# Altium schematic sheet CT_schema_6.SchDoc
size 266 x 267 mm
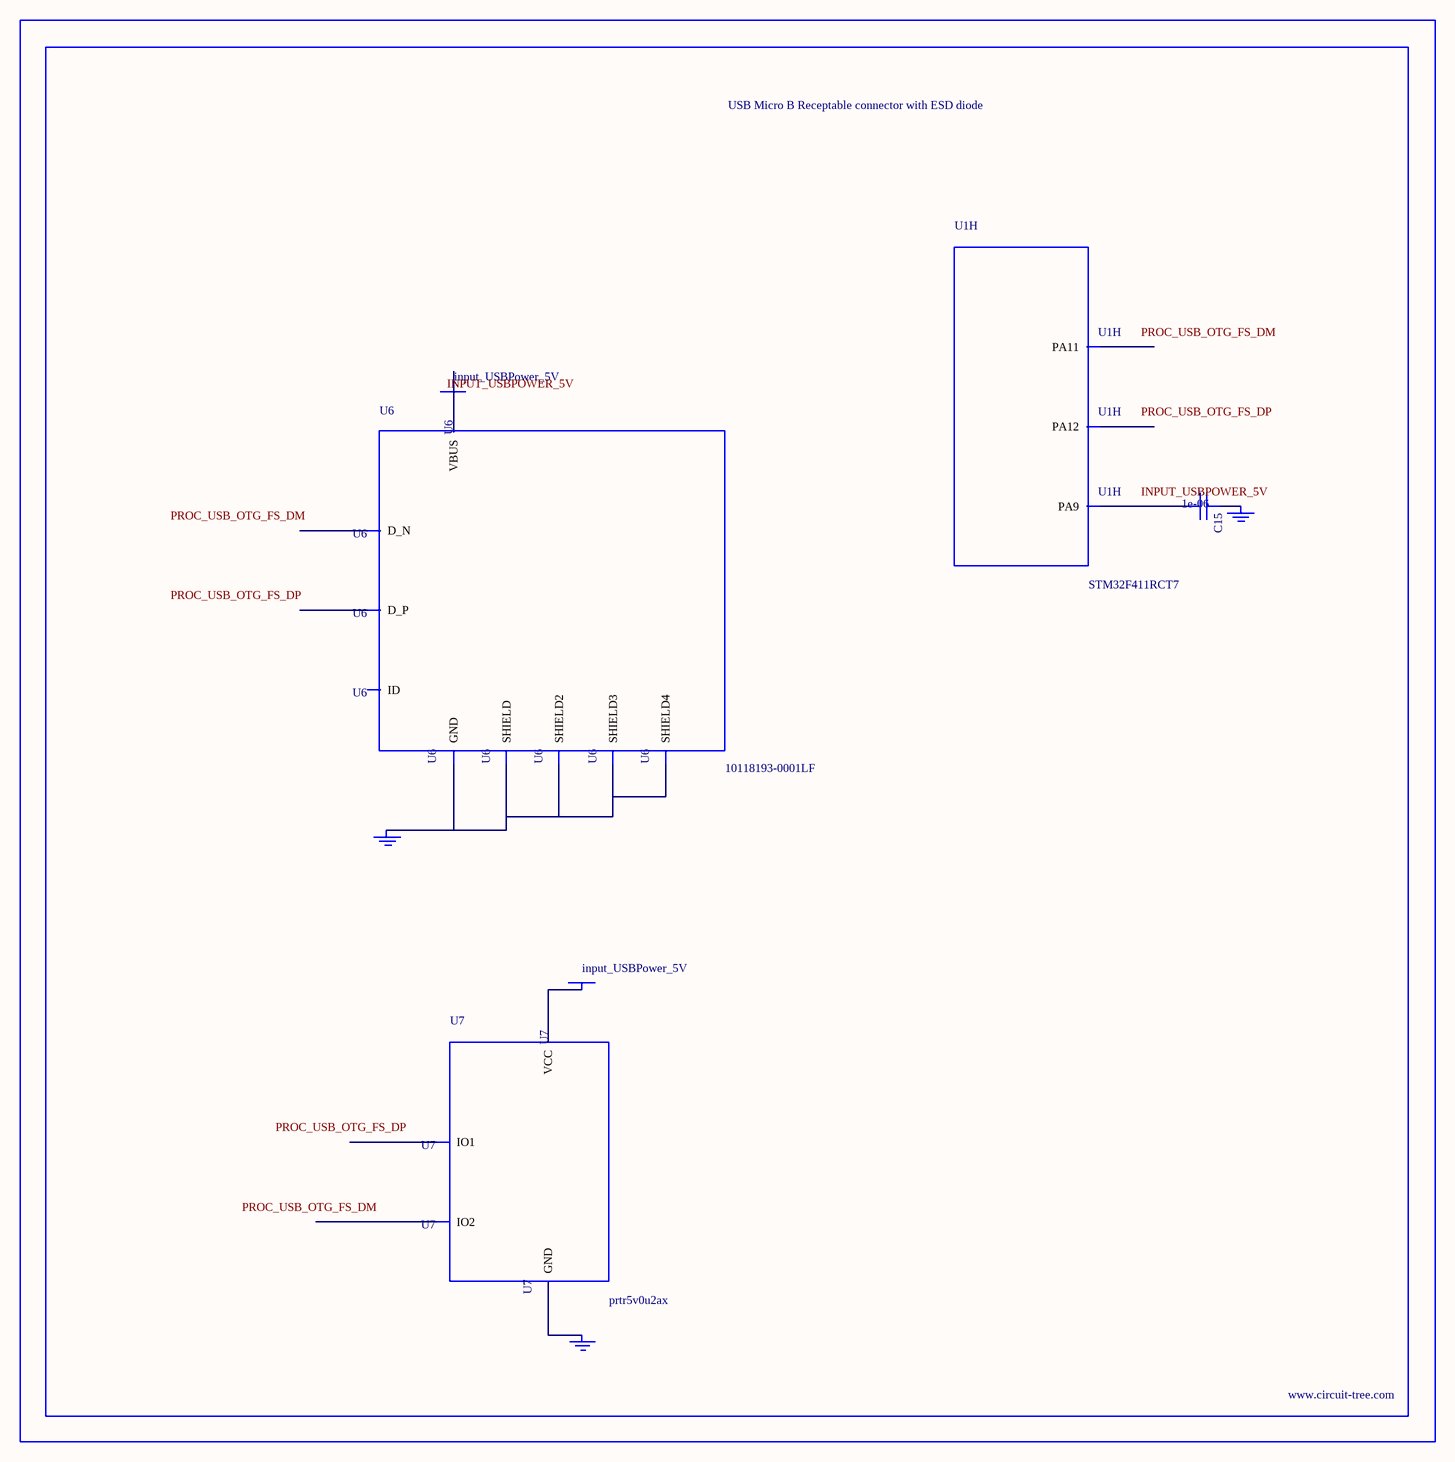
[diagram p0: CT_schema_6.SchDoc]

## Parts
BORDER5  (no value)
C15  1e-06  [C0603]
GND_INSTANCE_5_0  (no value)
GND_INSTANCE_5_1  (no value)
GND_INSTANCE_5_2  (no value)
POWER_INSTANCE_5_0  input_USBPower_5V
POWER_INSTANCE_5_1  input_USBPower_5V
U1  STM32F411RCT7  [LQFP64]  (part H of 8)
U6  10118193-0001LF  [FCI_10118193-0001LF]
U7  prtr5v0u2ax  [SOT143B]

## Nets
NetC15_1: C15.1 GND_INSTANCE_5_1.0(GND)
NetC15_2: C15.2 U1.42(PA9)
NetGND_INSTANCE_5_0_0: GND_INSTANCE_5_0.0(GND) U6.5(GND) U6.6(SHIELD) U6.7(SHIELD2) U6.8(SHIELD3) U6.9(SHIELD4)
NetGND_INSTANCE_5_2_0: GND_INSTANCE_5_2.0(GND) U7.1(GND)
NetPOWER_INSTANCE_5_0_0: POWER_INSTANCE_5_0.0(PWR) U6.1(VBUS)
NetPOWER_INSTANCE_5_1_0: POWER_INSTANCE_5_1.0(PWR) U7.4(VCC)

Not connected (* = marked no-connect by the designer): U1 44(PA11) 45(PA12); U6 2(D_N) 3(D_P) 4(ID); U7 2(IO1) 3(IO2)

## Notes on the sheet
- Labels drawn without touching a wire or pin: INPUT_USBPOWER_5V, PROC_USB_OTG_FS_DM, PROC_USB_OTG_FS_DP

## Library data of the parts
BORDER5 = BORDER_PAGE5
C15 = C0603C105K3RACTU
GND_INSTANCE_5_0-GND_INSTANCE_5_2 = GND
POWER_INSTANCE_5_0 POWER_INSTANCE_5_1 = PWR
